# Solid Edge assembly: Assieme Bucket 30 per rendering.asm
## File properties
Title: BUCKET 30
Author: DESYS
Template: Iso Assembly.asm
Last saved by: PIM_1
Revision: 12
Application: Solid Edge
Tipo di contenuto documento: 1
Document Number: 8801
Revision: 0
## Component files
Lavabo Bucket 30.par
Boccola portaasciugamani.par
Perno filettato.par
Portasciugamano Bucket 30.par
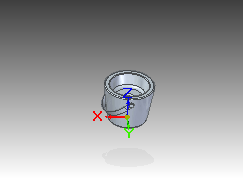
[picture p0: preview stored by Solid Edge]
